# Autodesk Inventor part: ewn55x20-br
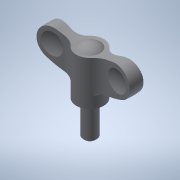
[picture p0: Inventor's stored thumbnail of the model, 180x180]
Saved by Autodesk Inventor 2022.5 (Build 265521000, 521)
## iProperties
Created: 2016-12
Part Number: ewn55x20-br
Material: 一般
Document SubType Name: Modeling
Designer: imaocorp
Density: 1 g/cm^3
Appearance: 既定
Author: imaocorp
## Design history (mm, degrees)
node "ewn55x20-br.x_t1"
node "ewn55x20-br"
node "Base1"
